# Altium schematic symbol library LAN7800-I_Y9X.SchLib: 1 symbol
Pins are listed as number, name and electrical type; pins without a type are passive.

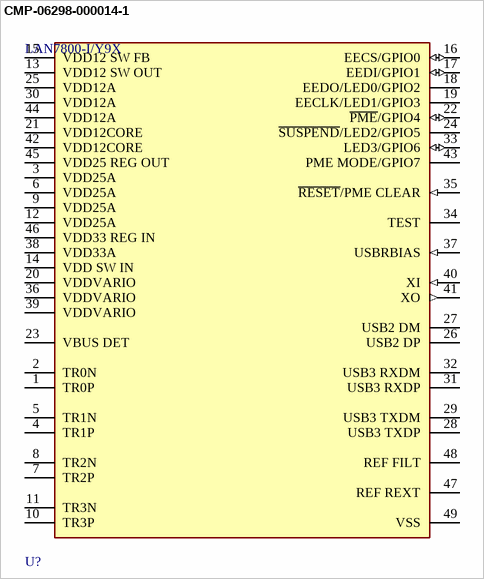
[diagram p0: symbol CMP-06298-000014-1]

## CMP-06298-000014-1
designator U?, comment LAN7800-I/Y9X
IC ETHERNET CTLR USB 48SQFN; Operating Supply Current: 4mA
footprint FP-48SQFN-5304-7x7B-IPC_B
footprint FP-48SQFN-5304-7x7B-IPC_A
footprint FP-48SQFN-5304-7x7B-IPC_C
footprint FP-48SQFN-5304-7x7B-MFG
pins: 1 TR0P, 2 TR0N, 3 VDD25A (power), 4 TR1P, 5 TR1N, 6 VDD25A (power), 7 TR2P, 8 TR2N, 9 VDD25A (power), 10 TR3P, 11 TR3N, 12 VDD25A (power), 13 VDD12 SW OUT (power), 14 VDD SW IN (power), 15 VDD12 SW FB (power), 16 EECS/GPIO0 (io), 17 EEDI/GPIO1 (io), 18 EEDO/LED0/GPIO2, 19 EECLK/LED1/GPIO3, 20 VDDVARIO (power), 21 VDD12CORE (power), 22 ~{PME}/GPIO4 (io), 23 VBUS DET (power), 24 ~{SUSPEND}/LED2/GPIO5, 25 VDD12A (power), 26 USB2 DP, 27 USB2 DM, 28 USB3 TXDP, 29 USB3 TXDM, 30 VDD12A (power), 31 USB3 RXDP, 32 USB3 RXDM, 33 LED3/GPIO6 (io), 34 TEST, 35 ~{RESET}/PME CLEAR (in), 36 VDDVARIO (power), 37 USBRBIAS (in), 38 VDD33A (power), 39 VDDVARIO (power), 40 XI (in), 41 XO (out), 42 VDD12CORE (power), 43 PME MODE/GPIO7, 44 VDD12A (power), 45 VDD25 REG OUT (power), 46 VDD33 REG IN (power), 47 REF REXT, 48 REF FILT, 49 VSS (power)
